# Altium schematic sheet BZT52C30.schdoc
size 127 x 101 mm
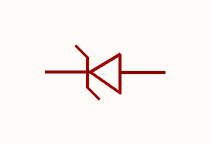
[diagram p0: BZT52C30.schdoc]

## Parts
ZD?  bzt52c30  [SOD-123_L2.8-W1.8-LS3.7-RD]  (value not drawn)

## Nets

Not connected (* = marked no-connect by the designer): ZD? 1(K) 2(A)

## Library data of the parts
ZD? = bzt52c30: 二极管配置:1个独立式;稳压值(标称值):30V;稳压值(范围):28V~32V;耗散功率(Pd):500mW;; Manufacturer: CJ(江苏长电/长晶); AddInBom: yes; ModelId: 7884390a25fb4c08947731ebfba7e3f8; ModelTransform: 144.8816,62.992,0,0,0,0,0,0,0; Diode Configuration: 1个独立式; Zener Voltage(Nom): 30V; Reverse Leakage Current (Ir): 100nA; Pd - Power Dissipation: 500mW; Impedance(Zzt): 80Ω; Impedance(Zzk): 300Ω; Operating Junction Temperature Range: -55℃~+150℃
